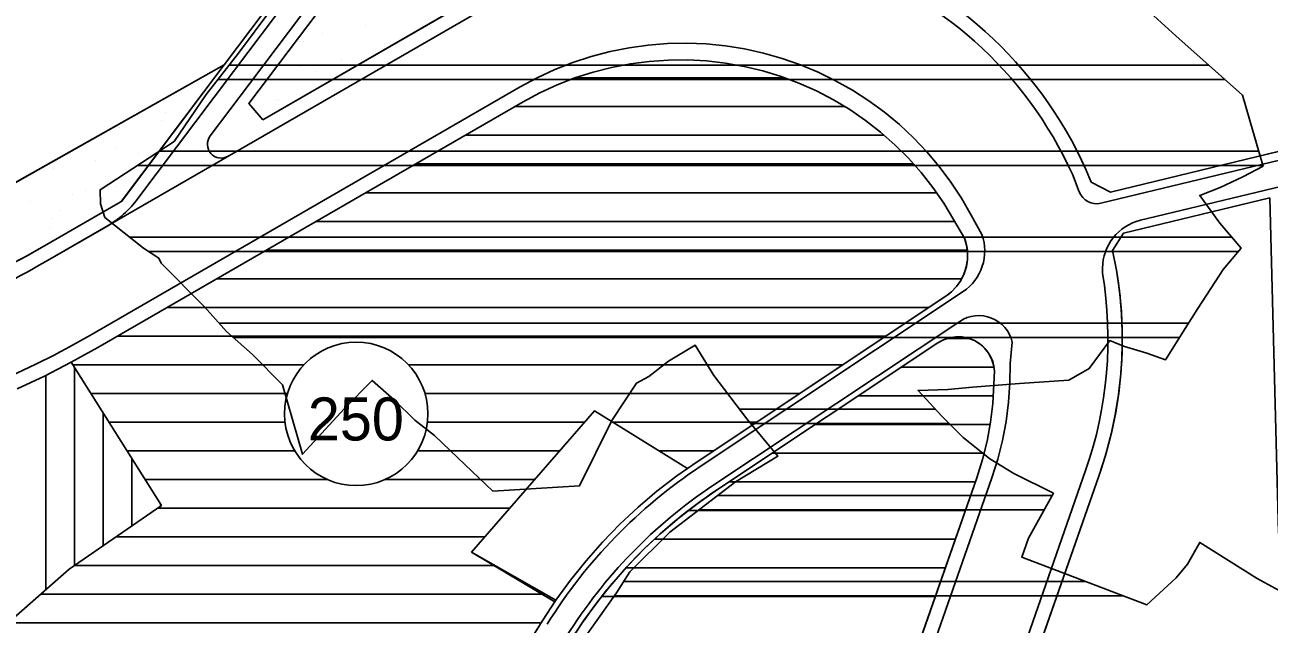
# Model space of a CAD drawing. Extents: x 427903 to 430077, y 4477233 to 4480385.
# Drawn here: x 428396.6 to 428830.3, y 4478826.1 to 4479035 of the extents above; entities that cross this region are included whole.
import ezdxf

# ---------------------------------------------------------------- set-up
doc = ezdxf.new("R2010")
doc.units = 0
for name, color, linetype in [('ADAKENARI', 7, 'Continuous'), ('KALDIRIM', 7, 'Continuous'), ('KALDIRIM2', 7, 'Continuous'), ('PL_AYA_BOLGE_PARKI', 7, 'Continuous'), ('PL_AYA_PARK_DINLENME', 7, 'Continuous'), ('PL_KON_MEV_350', 7, 'Continuous'), ('PL_KON_ONE_100', 7, 'Continuous'), ('PL_KON_ONE_250', 7, 'Continuous'), ('SIT_1_DER_ARKEOLOJIK', 7, 'Continuous'), ('SIT_SINIRI', 7, 'Continuous'), ('SM_DAIRE', 7, 'Continuous'), ('SM_TAKS', 7, 'Continuous'), ('TR_2_SITKORUMA', 7, 'Continuous'), ('TR_AZYOGUNKONUT', 7, 'Continuous'), ('TR_ORTAGELISME', 7, 'Continuous'), ('TR_ORTAYOGUNKONUT', 7, 'Continuous'), ('TR_PARKALANI', 7, 'Continuous')]:
    doc.layers.add(name, color=color, linetype=linetype)

msp = doc.modelspace()

# ---------------------------------------------------------------- linework, layer by layer
at = {"layer": 'ADAKENARI'}
for p, q in [((428498.91, 4479064.71), (428466.09, 4479021.09)), ((428474.66, 4479007.54), (428512.47, 4479057.79)), ((428563.16, 4479050.23), (428479.52, 4479001.93)), ((428466.09, 4479021.09), (428361.62, 4478962.24)), ((428466.09, 4479021.09), (428361.62, 4478962.24)), ((428466.09, 4479021.09), (428430.27, 4478973.48)), ((428594.68, 4479018.52), (428601.13, 4479020.17)), ((428601.13, 4479020.17), (428607.66, 4479021.42)), ((428607.66, 4479021.42), (428614.26, 4479022.27)), ((428614.26, 4479022.27), (428620.9, 4479022.73)), ((428620.9, 4479022.73), (428627.56, 4479022.77)), ((428627.56, 4479022.77), (428634.2, 4479022.42)), ((428634.2, 4479022.42), (428640.82, 4479021.66)), ((428640.82, 4479021.66), (428647.37, 4479020.5)), ((428647.37, 4479020.5), (428653.84, 4479018.94)), ((428653.84, 4479018.94), (428660.21, 4479016.99)), ((428582.14, 4479014.07), (428588.34, 4479016.48)), ((428588.34, 4479016.48), (428594.68, 4479018.52)), ((428660.21, 4479016.99), (428666.44, 4479014.67)), ((428666.44, 4479014.67), (428672.52, 4479011.96)), ((428570.23, 4479008.12), (428576.1, 4479011.28)), ((428576.1, 4479011.28), (428582.14, 4479014.07)), ((428672.52, 4479011.96), (428678.43, 4479008.89)), ((428421.96, 4478922.5), (428570.23, 4479008.12)), ((428479.52, 4479001.93), (428474.66, 4479007.54)), ((428678.43, 4479008.89), (428684.14, 4479005.47)), ((428684.14, 4479005.47), (428689.63, 4479001.71)), ((428689.63, 4479001.71), (428694.88, 4478997.62)), ((428694.88, 4478997.62), (428699.87, 4478993.23)), ((428864.53, 4478998.28), (428830.14, 4478989.99)), ((428699.87, 4478993.23), (428704.59, 4478988.53)), ((428830.14, 4478989.99), (428775.05, 4478976.72)), ((428704.59, 4478988.53), (428709.02, 4478983.56)), ((428766.6, 4478984.35), (428768.3, 4478980.17)), ((428709.02, 4478983.56), (428713.13, 4478978.33)), ((428775.05, 4478976.72), (428768.3, 4478980.17)), ((428713.13, 4478978.33), (428716.92, 4478972.85)), ((428429.74, 4478973.19), (428402.58, 4478957.5)), ((428430.27, 4478973.49), (428429.74, 4478973.19)), ((428716.92, 4478972.85), (428720.37, 4478967.16)), ((428779.53, 4478962.37), (428830.55, 4478974.66)), ((428720.37, 4478967.16), (428724.13, 4478960.65)), ((428775.71, 4478956.3), (428779.53, 4478962.37)), ((428777.15, 4478949.48), (428775.71, 4478956.3)), ((428717.63, 4478940.41), (428630.9, 4478882.72)), ((428638, 4478873.03), (428714.85, 4478924.15)), ((428421.96, 4478922.5), (428412.74, 4478917.39)), ((428412.74, 4478917.39), (428403.36, 4478912.58)), ((428444.17, 4478867.46), (428412.74, 4478917.39)), ((428403.36, 4478912.58), (428393.82, 4478908.1)), ((428734.62, 4478914.29), (428734.07, 4478903.06)), ((428734.07, 4478903.06), (428733.25, 4478896.46)), ((428552.29, 4478851.21), (428595.14, 4478900.42)), ((428595.14, 4478900.42), (428627.54, 4478880.37)), ((428733.25, 4478896.46), (428732.03, 4478889.92)), ((428732.03, 4478889.92), (428730.41, 4478883.46)), ((428623.8, 4478877.75), (428627.54, 4478880.37)), ((428627.54, 4478880.37), (428630.9, 4478882.72)), ((428730.41, 4478883.46), (428728.41, 4478877.11)), ((428616.94, 4478872.45), (428623.8, 4478877.75)), ((428728.41, 4478877.11), (428664.89, 4478695.48)), ((428720.37, 4478732.95), (428771.09, 4478878)), ((428610.34, 4478866.83), (428616.94, 4478872.45)), ((428411.99, 4478845.23), (428444.17, 4478867.46)), ((428604.01, 4478860.9), (428610.34, 4478866.83)), ((428597.98, 4478854.68), (428604.01, 4478860.9)), ((428592.24, 4478848.18), (428597.98, 4478854.68)), ((428581.72, 4478834.41), (428552.29, 4478851.21)), ((428586.81, 4478841.42), (428592.24, 4478848.18)), ((428343.84, 4478785.29), (428411.99, 4478845.23)), ((428581.72, 4478834.41), (428586.81, 4478841.42)), ((428576.96, 4478827.16), (428581.72, 4478834.41)), ((428576.96, 4478827.16), (428551.25, 4478785.91))]:
    msp.add_line(p, q, dxfattribs=at)
for centre, radius, start, end in [((428635.16, 4478925.53), 143.99, 24.1086, 120.0039), ((428708.19, 4478954.61), 17.05, 303.6311, 20.7693), ((428263.4, 4479198.54), 278.34, 284.5655, 300.0039), ((428635.16, 4478925.53), 143.99, 340.7273, 9.5763), ((428721.91, 4478913.55), 12.74, 3.3597, 123.6311), ((428734.1, 4478728.56), 173.51, 123.6311, 148.0612)]:
    msp.add_arc(centre, radius, start, end, dxfattribs=at)
at = {"layer": 'KALDIRIM'}
for p, q in [((428404.46, 4478952.81), (428565.66, 4479045.9)), ((428613.87, 4479027.93), (428607.19, 4479027)), ((428620.6, 4479028.47), (428613.87, 4479027.93)), ((428627.35, 4479028.6), (428620.6, 4479028.47)), ((428634.1, 4479028.33), (428627.35, 4479028.6)), ((428640.81, 4479027.67), (428634.1, 4479028.33)), ((428647.48, 4479026.6), (428640.81, 4479027.67)), ((428594.04, 4479023.96), (428587.62, 4479021.86)), ((428600.57, 4479025.68), (428594.04, 4479023.96)), ((428607.19, 4479027), (428600.57, 4479025.68)), ((428654.07, 4479025.15), (428647.48, 4479026.6)), ((428660.57, 4479023.3), (428654.07, 4479025.15)), ((428666.94, 4479021.08), (428660.57, 4479023.3)), ((428581.34, 4479019.39), (428575.22, 4479016.55)), ((428587.62, 4479021.86), (428581.34, 4479019.39)), ((428673.17, 4479018.48), (428666.94, 4479021.08)), ((428575.22, 4479016.55), (428569.28, 4479013.34)), ((428679.23, 4479015.51), (428673.17, 4479018.48)), ((428685.11, 4479012.19), (428679.23, 4479015.51)), ((428419.46, 4478926.83), (428569.28, 4479013.34)), ((428690.78, 4479008.53), (428685.11, 4479012.19)), ((428696.23, 4479004.54), (428690.78, 4479008.53)), ((428701.43, 4479000.24), (428696.23, 4479004.54)), ((428706.36, 4478995.63), (428701.43, 4479000.24)), ((428711.01, 4478990.74), (428706.36, 4478995.63)), ((428771.7, 4478972.82), (428865.24, 4478995.36)), ((428715.37, 4478985.58), (428711.01, 4478990.74)), ((428719.41, 4478980.17), (428715.37, 4478985.58)), ((428785.47, 4478966.88), (428867.35, 4478986.61)), ((428723.12, 4478974.54), (428719.41, 4478980.17)), ((428761.75, 4478982.93), (428764.11, 4478976.81)), ((428726.5, 4478968.69), (428723.12, 4478974.54)), ((428730.21, 4478961.91), (428726.5, 4478968.69)), ((428772.26, 4478948.45), (428772.29, 4478950.16)), ((428632.01, 4478881.06), (428723.63, 4478942)), ((428636.44, 4478874.39), (428722.48, 4478931.63)), ((428740.07, 4478916.93), (428740.82, 4478924.34)), ((428740, 4478910.18), (428740.07, 4478916.93)), ((428739.53, 4478903.45), (428740, 4478910.18)), ((428738.67, 4478896.76), (428739.53, 4478903.45)), ((428737.4, 4478890.12), (428738.67, 4478896.76)), ((428735.75, 4478883.58), (428737.4, 4478890.12)), ((428733.71, 4478877.14), (428735.75, 4478883.58)), ((428733.71, 4478877.14), (428669.61, 4478693.83)), ((428766.37, 4478879.65), (428702.2, 4478696.13))]:
    msp.add_line(p, q, dxfattribs=at)
for centre, radius, start, end in [((428635.16, 4478925.53), 139, 24.3922, 120.0039), ((428770.18, 4478979.15), 6.5, 201.088, 283.5479), ((428789.5, 4478950.16), 17.2, 103.5479, 179.9933), ((428714.22, 4478956.16), 17, 303.6311, 19.7927), ((428265.44, 4479193.55), 277.99, 286.1161, 300.0039), ((428635.16, 4478925.53), 139, 340.7273, 9.4927), ((428729.13, 4478921.64), 12, 12.9987, 123.6311), ((428265.44, 4479193.55), 307.99, 285.6869, 300.0039), ((428732.25, 4478730.36), 180.99, 123.6311, 148.0612), ((428732.25, 4478730.36), 172.99, 123.6311, 148.0612)]:
    msp.add_arc(centre, radius, start, end, dxfattribs=at)
at = {"layer": 'KALDIRIM2'}
for p, q in [((428502.52, 4479062.86), (428469.28, 4479018.69)), ((428508.85, 4479059.63), (428474.88, 4479014.48)), ((428469.28, 4479018.69), (428435.99, 4478974.43)), ((428474.88, 4479014.48), (428461.17, 4478996.26)), ((428404.46, 4478952.81), (428424.9, 4478964.61))]:
    msp.add_line(p, q, dxfattribs=at)
for centre, radius, start, end in [((428465.03, 4478993.36), 4.83, 143.0408, 300.0041), ((428406.35, 4478996.74), 37.09, 300.0041, 323.0408), ((428265.44, 4479193.55), 277.99, 286.1333, 300.0041)]:
    msp.add_arc(centre, radius, start, end, dxfattribs=at)
at = {"layer": 'PL_AYA_BOLGE_PARKI'}
for points in [[(428900.92, 4479004.53), (428894.56, 4479065.47), (428760.51, 4479082.67), (428607.5, 4479102.3), (428599.98, 4479103.07), (428592.44, 4479103.47), (428584.89, 4479103.5), (428577.34, 4479103.15), (428569.82, 4479102.43), (428562.35, 4479101.34), (428554.94, 4479099.87), (428547.61, 4479098.04), (428540.38, 4479095.85), (428533.27, 4479093.31), (428526.56, 4479090.52), (428520.47, 4479083.83), (428512.47, 4479057.79), (428474.66, 4479007.54), (428479.52, 4479001.93)], [(428479.52, 4479001.93), (428563.16, 4479050.23)], [(428402.58, 4478957.5), (428429.74, 4478973.19), (428430.26, 4478973.49), (428430.27, 4478973.49), (428466.09, 4479021.09), (428361.62, 4478962.24), (428299.56, 4478998.87), (428264.07, 4478976.56), (428266.36, 4478967.22), (428278.01, 4478919.92), (428284.03, 4478916.32), (428284.04, 4478916.33), (428292.91, 4478918.63), (428293.13, 4478919.15), (428292.91, 4478918.63), (428333.4, 4478929.15)], [(428766.6, 4478984.35), (428768.3, 4478980.17), (428775.05, 4478976.72), (428830.14, 4478989.99), (428864.53, 4478998.28)], [(428720.37, 4478732.95), (428771.09, 4478878), (428773.31, 4478884.9), (428775.18, 4478891.91), (428776.69, 4478899), (428777.85, 4478906.15), (428778.64, 4478913.36), (428779.07, 4478920.6), (428779.14, 4478927.84), (428778.84, 4478935.09), (428778.18, 4478942.31), (428777.15, 4478949.48), (428775.71, 4478956.3), (428779.53, 4478962.37), (428830.55, 4478974.66), (428833.67, 4478857.87), (428874.66, 4478802.53), (428962.79, 4478861.97), (428999.68, 4478767.69)]]:
    msp.add_lwpolyline(points, dxfattribs=at)
for centre, radius, start, end in [((428635.16, 4478925.53), 143.99, 24.1086, 120.0039), ((428263.4, 4479198.54), 278.34, 285.613, 300.0039)]:
    msp.add_arc(centre, radius, start, end, dxfattribs=at)
at = {"layer": 'PL_AYA_PARK_DINLENME'}
msp.add_lwpolyline([(428616.94, 4478872.45), (428610.34, 4478866.83), (428604.01, 4478860.9), (428597.98, 4478854.68), (428592.24, 4478848.18), (428586.81, 4478841.42), (428581.72, 4478834.41), (428581.36, 4478833.86), (428552.29, 4478851.21), (428595.14, 4478900.42), (428627.54, 4478880.37), (428623.8, 4478877.75)], close=True, dxfattribs=at)
at = {"layer": 'PL_KON_MEV_350'}
msp.add_lwpolyline([(428393.82, 4478908.1), (428403.36, 4478912.58), (428412.74, 4478917.39), (428444.17, 4478867.46), (428411.99, 4478845.23), (428343.84, 4478785.29)], dxfattribs=at)
at = {"layer": 'PL_KON_ONE_100'}
msp.add_lwpolyline([(428412.82, 4479078.87), (428337.6, 4479052.91), (428245.8, 4479030.61), (428161.23, 4479010.05), (428153.73, 4479002.08), (428148.66, 4478973.65), (428150.94, 4478971.76), (428192.16, 4478987.37), (428251.89, 4478986.28), (428264.07, 4478976.56), (428299.56, 4478998.87), (428361.62, 4478962.24), (428466.09, 4479021.09), (428498.91, 4479064.71), (428518.19, 4479127.46), (428510.04, 4479134), (428456.71, 4479103.76), (428412.82, 4479078.87)], dxfattribs=at)
at = {"layer": 'PL_KON_ONE_250'}
for points in [[(428551.25, 4478785.91), (428576.96, 4478827.16), (428581.72, 4478834.41), (428552.29, 4478851.21), (428595.14, 4478900.42), (428627.54, 4478880.37), (428630.9, 4478882.72), (428717.63, 4478940.41), (428719.64, 4478941.98), (428721.4, 4478943.83), (428722.86, 4478945.92), (428723.99, 4478948.2), (428724.77, 4478950.62), (428725.18, 4478953.14), (428725.21, 4478955.69), (428724.85, 4478958.21), (428724.13, 4478960.65), (428720.37, 4478967.16), (428716.92, 4478972.85), (428713.13, 4478978.33), (428709.02, 4478983.56), (428704.59, 4478988.53), (428699.87, 4478993.23), (428694.88, 4478997.62), (428689.63, 4479001.71), (428684.14, 4479005.47), (428678.43, 4479008.89), (428672.52, 4479011.96), (428666.44, 4479014.67), (428660.21, 4479016.99), (428653.84, 4479018.94), (428647.37, 4479020.5), (428640.82, 4479021.66), (428634.2, 4479022.42), (428627.56, 4479022.77), (428620.9, 4479022.73), (428614.26, 4479022.27), (428607.66, 4479021.42), (428601.13, 4479020.17), (428594.68, 4479018.52), (428588.34, 4479016.48), (428582.14, 4479014.07), (428576.1, 4479011.28), (428570.23, 4479008.12), (428421.96, 4478922.5), (428412.74, 4478917.39), (428444.17, 4478867.46), (428411.99, 4478845.23), (428343.84, 4478785.29)], [(428586.85, 4478820.35), (428591.37, 4478827.22), (428596.2, 4478833.87), (428601.34, 4478840.28), (428606.78, 4478846.45), (428612.51, 4478852.34), (428618.5, 4478857.96), (428624.76, 4478863.29), (428631.27, 4478868.32), (428638, 4478873.03), (428714.85, 4478924.15), (428716.81, 4478925.22), (428718.92, 4478925.93), (428721.12, 4478926.26), (428723.34, 4478926.2), (428725.52, 4478925.76), (428727.59, 4478924.95), (428729.49, 4478923.78), (428731.15, 4478922.31), (428732.54, 4478920.56), (428733.6, 4478918.61), (428734.3, 4478916.5), (428734.62, 4478914.29), (428734.07, 4478903.06), (428733.25, 4478896.46), (428732.03, 4478889.92), (428730.41, 4478883.46), (428728.41, 4478877.11), (428664.89, 4478695.48)]]:
    msp.add_lwpolyline(points, dxfattribs=at)
at = {"layer": 'SIT_1_DER_ARKEOLOJIK'}
for points in [[(428592.86, 4478822.94), (428602.83, 4478836.96), (428607.47, 4478844.38), (428621.38, 4478858.17), (428644.33, 4478875.68), (428659.05, 4478884.6), (428648.27, 4478897.7), (428636.79, 4478912.77), (428630.3, 4478923.32), (428620.91, 4478917.75), (428614.08, 4478912.42), (428609.79, 4478910.1), (428601.21, 4478897.12), (428589.96, 4478874.29), (428559.71, 4478872.43), (428547.54, 4478884.02), (428539.43, 4478891.91), (428532.47, 4478897.24), (428525.4, 4478904.19), (428517.63, 4478911.03), (428508.01, 4478901.29), (428493.41, 4478885.3), (428486.34, 4478909.52), (428475.9, 4478920.07), (428466.86, 4478928.07), (428459.21, 4478936.76), (428444.03, 4478951.95), (428443.23, 4478953.69), (428437.89, 4478957.11), (428424.43, 4478967.87), (428422.98, 4478972.65), (428422.8, 4478977.53), (428448.64, 4478994.34), (428459.76, 4479010.69), (428471.05, 4479025.15), (428482.26, 4479040.24)], [(428790.1, 4479038.16), (428797.87, 4479031.21), (428821.1, 4479010.51), (428827.28, 4478989.17), (428828.23, 4478985.76), (428821.19, 4478982.05), (428813.33, 4478978.26), (428806.19, 4478975.55), (428813.14, 4478965.88), (428820.55, 4478957.2), (428814.38, 4478949.75), (428805.45, 4478936.07), (428801.05, 4478929.11), (428794.21, 4478918.22), (428787.72, 4478920.54), (428779.6, 4478922.97), (428774.85, 4478924.94), (428767.66, 4478915.2), (428760.48, 4478911.15), (428743.32, 4478909.99), (428726.98, 4478908.71), (428718.28, 4478907.9), (428707.97, 4478907.55), (428716.2, 4478898.63), (428723.73, 4478891.21), (428733, 4478883.68), (428741.35, 4478878.57), (428755.14, 4478871.74), (428746.45, 4478856.09), (428744.13, 4478849.48), (428787.72, 4478832.79), (428797.92, 4478842.29), (428801.86, 4478847.05), (428806.15, 4478854.58), (428826.2, 4478841.95), (428833.85, 4478837.77)]]:
    msp.add_lwpolyline(points, dxfattribs=at)
at = {"layer": 'SIT_SINIRI'}
msp.add_line((428823.9, 4479000.85), (428825.88, 4478994.16), dxfattribs=at)
msp.add_line((428823.9, 4479000.85), (428825.88, 4478994.16), dxfattribs=at)
at = {"layer": 'SM_DAIRE'}
msp.add_circle((428512.08, 4478899.39), 25, dxfattribs=at)
at = {"layer": 'TR_2_SITKORUMA'}
for p, q in [((428467.79, 4479020.98), (428809.35, 4479020.98)), ((428463.88, 4479015.98), (428814.97, 4479015.98)), ((428443.47, 4478990.98), (428826.76, 4478990.98)), ((428435.78, 4478985.98), (428828.17, 4478985.98)), ((428433.05, 4478960.98), (428817.33, 4478960.98)), ((428439.66, 4478955.98), (428819.54, 4478955.98)), ((428464.31, 4478930.98), (428802.23, 4478930.98)), ((428469.23, 4478925.98), (428799.08, 4478925.98)), ((428645.78, 4478900.98), (428714.03, 4478900.98)), ((428645.78, 4478900.98), (428714.03, 4478900.98)), ((428649.69, 4478895.98), (428718.89, 4478895.98)), ((428649.69, 4478895.98), (428718.89, 4478895.98)), ((428638.17, 4478870.98), (428754.72, 4478870.98)), ((428631.61, 4478865.98), (428751.95, 4478865.98)), ((428605.34, 4478840.98), (428766.34, 4478840.98)), ((428602.13, 4478835.98), (428779.39, 4478835.98))]:
    msp.add_line(p, q, dxfattribs=at)
at = {"layer": 'TR_AZYOGUNKONUT'}
msp.add_lwpolyline([(428456.71, 4479103.76), (428412.82, 4479078.87), (428337.6, 4479052.91), (428245.8, 4479030.61), (428161.23, 4479010.05), (428153.73, 4479002.08), (428148.66, 4478973.65), (428150.94, 4478971.76), (428192.16, 4478987.37), (428251.89, 4478986.28), (428264.07, 4478976.56), (428299.56, 4478998.87), (428361.62, 4478962.24), (428466.09, 4479021.09), (428498.91, 4479064.71), (428518.19, 4479127.46), (428510.04, 4479134), (428456.71, 4479103.76)], dxfattribs=at)
at = {"layer": 'TR_ORTAGELISME'}
for p, q in [((428588.39, 4479016.5), (428661.53, 4479016.5)), ((428567.42, 4479006.5), (428682.42, 4479006.5)), ((428550.1, 4478996.5), (428696.16, 4478996.5)), ((428532.79, 4478986.5), (428706.4, 4478986.5)), ((428515.47, 4478976.5), (428714.4, 4478976.5)), ((428498.15, 4478966.5), (428720.75, 4478966.5)), ((428480.83, 4478956.5), (428725.09, 4478956.5)), ((428463.51, 4478946.5), (428723.15, 4478946.5)), ((428446.2, 4478936.5), (428711.75, 4478936.5)), ((428428.88, 4478926.5), (428696.72, 4478926.5)), ((428718.19, 4478925.68), (428725.72, 4478925.68)), ((428413.3, 4478916.5), (428493.86, 4478916.5)), ((428530.31, 4478916.5), (428681.68, 4478916.5)), ((428702.12, 4478915.68), (428734.42, 4478915.68)), ((428419.6, 4478906.5), (428488.12, 4478906.5)), ((428536.05, 4478906.5), (428666.65, 4478906.5)), ((428687.09, 4478905.68), (428734.2, 4478905.68)), ((428425.89, 4478896.5), (428487.25, 4478896.5)), ((428536.92, 4478896.5), (428591.73, 4478896.5)), ((428601.48, 4478896.5), (428651.62, 4478896.5)), ((428672.05, 4478895.68), (428733.1, 4478895.68)), ((428432.19, 4478886.5), (428490.66, 4478886.5)), ((428533.51, 4478886.5), (428583.02, 4478886.5)), ((428617.64, 4478886.5), (428636.58, 4478886.5)), ((428657.02, 4478885.68), (428730.97, 4478885.68)), ((428438.48, 4478876.5), (428502.03, 4478876.5)), ((428522.14, 4478876.5), (428574.31, 4478876.5)), ((428641.99, 4478875.68), (428727.91, 4478875.68)), ((428442.78, 4478866.5), (428565.6, 4478866.5)), ((428627.86, 4478865.68), (428724.41, 4478865.68)), ((428428.3, 4478856.5), (428556.89, 4478856.5)), ((428616.07, 4478855.68), (428720.91, 4478855.68)), ((428413.83, 4478846.5), (428560.54, 4478846.5)), ((428606.11, 4478845.68), (428717.42, 4478845.68)), ((428402.06, 4478836.5), (428578.05, 4478836.5)), ((428597.65, 4478835.68), (428713.92, 4478835.68)), ((428390.7, 4478826.5), (428576.55, 4478826.5))]:
    msp.add_line(p, q, dxfattribs=at)
at = {"layer": 'TR_ORTAYOGUNKONUT'}
for p, q in [((428413.84, 4478846.51), (428413.84, 4478915.64)), ((428403.84, 4478838.06), (428403.84, 4478912.83)), ((428423.84, 4478853.42), (428423.84, 4478899.76)), ((428433.84, 4478860.32), (428433.84, 4478883.87)), ((428443.84, 4478867.23), (428443.84, 4478867.99))]:
    msp.add_line(p, q, dxfattribs=at)
at = {"layer": 'TR_PARKALANI'}
for p, q in [((428500.45, 4479032.03), (428500.45, 4479032.03)), ((428500.45, 4479032.03), (428500.45, 4479032.03)), ((428515.22, 4479034.64), (428515.22, 4479034.64)), ((428515.22, 4479034.64), (428515.22, 4479034.64)), ((428493.76, 4479029.1), (428493.76, 4479029.1)), ((428493.76, 4479029.1), (428493.76, 4479029.1)), ((428492.34, 4479020.45), (428492.34, 4479020.45)), ((428492.34, 4479020.45), (428492.34, 4479020.45)), ((428507.11, 4479023.05), (428507.11, 4479023.05)), ((428507.11, 4479023.05), (428507.11, 4479023.05)), ((428497.91, 4479018.8), (428497.91, 4479018.8)), ((428484.23, 4479008.86), (428484.23, 4479008.86)), ((428484.23, 4479008.86), (428484.23, 4479008.86)), ((428484.86, 4479008.59), (428484.86, 4479008.59)), ((428444.23, 4479001.81), (428444.23, 4479001.81)), ((428444.23, 4479001.81), (428444.23, 4479001.81)), ((428445.45, 4479004.55), (428445.45, 4479004.55)), ((428426.51, 4478997.66), (428426.51, 4478997.66)), ((428426.51, 4478997.66), (428426.51, 4478997.66)), ((428429.46, 4478999.2), (428429.46, 4478999.2)), ((428429.46, 4478999.2), (428429.46, 4478999.2)), ((428412.43, 4478990.07), (428412.43, 4478990.07)), ((428428.07, 4478992.39), (428428.07, 4478992.39)), ((428436.12, 4478990.22), (428436.12, 4478990.22)), ((428436.12, 4478990.22), (428436.12, 4478990.22)), ((428406.58, 4478985.01), (428406.58, 4478985.01)), ((428406.58, 4478985.01), (428406.58, 4478985.01)), ((428421.35, 4478987.62), (428421.35, 4478987.62)), ((428421.35, 4478987.62), (428421.35, 4478987.62)), ((428413.24, 4478976.03), (428413.24, 4478976.03)), ((428413.24, 4478976.03), (428413.24, 4478976.03)), ((428417.61, 4478977.15), (428417.61, 4478977.15)), ((428428.01, 4478978.64), (428428.01, 4478978.64)), ((428428.01, 4478978.64), (428428.01, 4478978.64)), ((428398.47, 4478973.43), (428398.47, 4478973.43)), ((428398.47, 4478973.43), (428398.47, 4478973.43)), ((428406.12, 4478967.51), (428406.12, 4478967.51)), ((428406.12, 4478967.51), (428406.12, 4478967.51)), ((428408.96, 4478970.37), (428408.96, 4478970.37)), ((428405.13, 4478964.45), (428405.13, 4478964.45)), ((428405.13, 4478964.45), (428405.13, 4478964.45))]:
    msp.add_line(p, q, dxfattribs=at)

# ---------------------------------------------------------------- texts
at = {"layer": 'SM_TAKS'}
msp.add_text('250', height=15, dxfattribs=at).set_placement((428495.22, 4478890.12))

doc.saveas('drawing.dxf')
